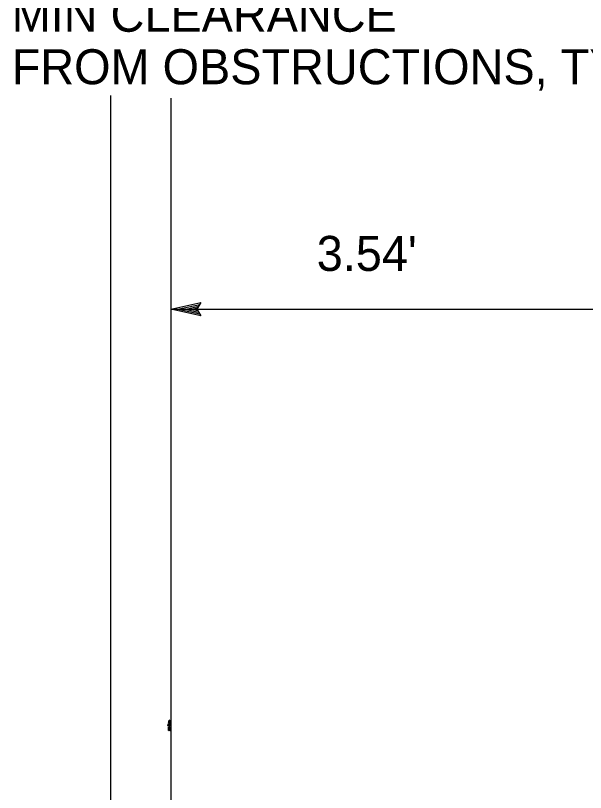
# Model space of a CAD drawing. Extents: x -1680 to 1155, y -802 to 799.
# Drawn here: x 88.5 to 202.4, y -549.1 to -393.8 of the extents above; entities that cross this region are included whole.
import ezdxf

# ---------------------------------------------------------------- set-up
doc = ezdxf.new("R2010")
doc.units = 0
doc.layers.add('Misc CnstDet(22)', color=7, linetype='Continuous')

msp = doc.modelspace()

# ---------------------------------------------------------------- linework, layer by layer
at = {"layer": 'Misc CnstDet(22)'}
for p, q in [((107.55, -409.77), (107.55, -496.97)), ((119.59, -410.3), (119.59, -496.61)), ((119.59, -452.5), (125.59, -451.17)), ((120.98, -452.5), (125.36, -451.53)), ((122.35, -452.51), (125.18, -451.88)), ((125.59, -451.17), (124.79, -452.5)), ((125.59, -451.17), (125.59, -451.17)), ((125.59, -453.84), (119.59, -452.5)), ((119.59, -452.5), (119.59, -452.5)), ((119.59, -452.5), (165.23, -452.5)), ((125.37, -453.49), (120.97, -452.51)), ((125.14, -453.13), (122.35, -452.51)), ((123.73, -452.51), (124.94, -452.24)), ((124.96, -452.78), (123.73, -452.51)), ((124.79, -452.5), (125.59, -453.84)), ((165.23, -452.5), (212.09, -452.5)), ((125.59, -453.84), (125.59, -453.84)), ((107.55, -496.97), (107.55, -590.18)), ((119.59, -496.61), (119.59, -590.18))]:
    msp.add_line(p, q, dxfattribs=at)
for points in [[(118.98, -535.56), (118.93, -535.6), (118.98, -535.6), (119.03, -535.56), (118.98, -535.56)], [(118.93, -535.6), (118.93, -535.64), (118.98, -535.64), (118.98, -535.6), (118.93, -535.6)], [(118.93, -535.62), (119.65, -535.62), (119.65, -535.64), (118.93, -535.64), (118.93, -535.62)], [(118.93, -535.64), (118.93, -535.68), (118.98, -535.68), (118.98, -535.64), (118.93, -535.64)], [(118.93, -535.68), (118.98, -535.72), (119.03, -535.72), (118.98, -535.68), (118.93, -535.68)], [(119.08, -535.52), (119.03, -535.54), (119.03, -535.56), (119.08, -535.54), (119.08, -535.52)], [(119.03, -535.7), (119.08, -535.72), (119.08, -535.74), (119.03, -535.72), (119.03, -535.7)], [(119.08, -535.29), (119.23, -534.62), (119.29, -534.62), (119.13, -535.29), (119.08, -535.29)], [(119.18, -535.5), (119.08, -535.52), (119.08, -535.54), (119.18, -535.52), (119.18, -535.5)], [(119.08, -535.72), (119.18, -535.74), (119.18, -535.76), (119.08, -535.74), (119.08, -535.72)], [(119.29, -535.21), (119.13, -535.27), (119.13, -535.29), (119.29, -535.23), (119.29, -535.21)], [(119.29, -535.5), (119.18, -535.5), (119.18, -535.52), (119.29, -535.52), (119.29, -535.5)], [(119.18, -535.74), (119.29, -535.74), (119.29, -535.76), (119.18, -535.76), (119.18, -535.74)], [(119.23, -534.62), (119.23, -536.62), (119.29, -536.62), (119.29, -534.62), (119.23, -534.62)], [(119.23, -534.62), (119.39, -535.29), (119.44, -535.29), (119.29, -534.62), (119.23, -534.62)], [(119.29, -535.25), (119.29, -534.7), (119.34, -534.7), (119.34, -535.25), (119.29, -535.25)], [(119.29, -535.25), (119.29, -534.81), (119.34, -534.81), (119.34, -535.25), (119.29, -535.25)], [(119.29, -535.27), (119.29, -534.91), (119.34, -534.91), (119.34, -535.27), (119.29, -535.27)], [(119.29, -535.21), (119.44, -535.27), (119.44, -535.29), (119.29, -535.23), (119.29, -535.21)], [(119.39, -535.5), (119.29, -535.5), (119.29, -535.52), (119.39, -535.52), (119.39, -535.5)], [(119.29, -535.74), (119.39, -535.74), (119.39, -535.76), (119.29, -535.76), (119.29, -535.74)], [(119.34, -535.27), (119.34, -535.01), (119.39, -535.01), (119.39, -535.27), (119.34, -535.27)], [(119.34, -535.29), (119.34, -535.11), (119.39, -535.11), (119.39, -535.29), (119.34, -535.29)], [(119.39, -535.29), (119.39, -535.21), (119.44, -535.21), (119.44, -535.29), (119.39, -535.29)], [(119.49, -535.52), (119.39, -535.5), (119.39, -535.52), (119.49, -535.54), (119.49, -535.52)], [(119.39, -535.74), (119.49, -535.72), (119.49, -535.74), (119.39, -535.76), (119.39, -535.74)], [(119.54, -535.54), (119.49, -535.52), (119.49, -535.54), (119.54, -535.56), (119.54, -535.54)], [(119.54, -535.6), (119.49, -535.56), (119.54, -535.56), (119.6, -535.6), (119.54, -535.6)], [(119.49, -535.72), (119.54, -535.68), (119.6, -535.68), (119.54, -535.72), (119.49, -535.72)], [(119.49, -535.72), (119.54, -535.7), (119.54, -535.72), (119.49, -535.74), (119.49, -535.72)], [(119.54, -535.64), (119.54, -535.6), (119.6, -535.6), (119.6, -535.64), (119.54, -535.64)], [(119.54, -535.68), (119.54, -535.64), (119.6, -535.64), (119.6, -535.68), (119.54, -535.68)], [(119.23, -535.99), (119.08, -536.07), (119.13, -536.07), (119.29, -535.99), (119.23, -535.99)], [(119.08, -536.05), (119.08, -536.68), (119.13, -536.68), (119.13, -536.05), (119.08, -536.05)], [(119.08, -536.07), (119.08, -536.68), (119.13, -536.68), (119.13, -536.07), (119.08, -536.07)], [(119.13, -536.03), (119.13, -536.66), (119.18, -536.66), (119.18, -536.03), (119.13, -536.03)], [(119.13, -536.05), (119.13, -536.66), (119.18, -536.66), (119.18, -536.05), (119.13, -536.05)], [(119.29, -536.6), (119.13, -536.66), (119.13, -536.68), (119.29, -536.62), (119.29, -536.6)], [(119.18, -536.01), (119.18, -536.64), (119.23, -536.64), (119.23, -536.01), (119.18, -536.01)], [(119.18, -536.03), (119.18, -536.64), (119.23, -536.64), (119.23, -536.03), (119.18, -536.03)], [(119.23, -535.99), (119.39, -536.07), (119.44, -536.07), (119.29, -535.99), (119.23, -535.99)], [(119.23, -536.01), (119.23, -536.62), (119.29, -536.62), (119.29, -536.01), (119.23, -536.01)], [(119.29, -536.6), (119.44, -536.66), (119.44, -536.68), (119.29, -536.62), (119.29, -536.6)], [(119.39, -536.07), (119.39, -536.68), (119.44, -536.68), (119.44, -536.07), (119.39, -536.07)]]:
    msp.add_lwpolyline(points, dxfattribs=at)

# ---------------------------------------------------------------- texts
for s, p in [('MIN CLEARANCE', (87.77, -397.02)), ('FROM OBSTRUCTIONS, TYP', (87.77, -407.52))]:
    msp.add_text(s, height=7, rotation=360, dxfattribs=at).set_placement(p)
msp.add_text("3.54'", height=7, dxfattribs=at).set_placement((148.74, -444.83))

doc.saveas('drawing.dxf')
